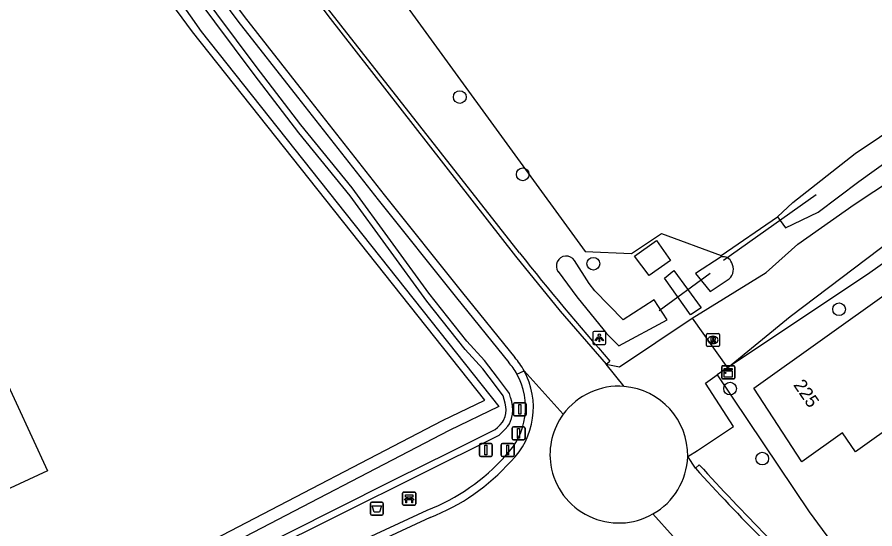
# Model space of a CAD drawing. Extents: x 164494 to 166241, y 382475 to 384494.
# Drawn here: x 165093.4 to 165159.3, y 383042.8 to 383082.1 of the extents above; entities that cross this region are included whole.
import ezdxf

# ---------------------------------------------------------------- set-up
doc = ezdxf.new("R2010")
doc.units = 0
for name, color, linetype in [('IMGEO_Afsluitpaal', 7, 'Continuous'), ('IMGEO_Afvalbak', 7, 'Continuous'), ('IMGEO_Bank', 7, 'Continuous'), ('IMGEO_Berm_halfverhard', 7, 'Continuous'), ('IMGEO_Boom', 7, 'Continuous'), ('IMGEO_Duiker', 7, 'Continuous'), ('IMGEO_Erf', 7, 'Continuous'), ('IMGEO_Grasland_overig', 7, 'Continuous'), ('IMGEO_Groenvoorziening', 7, 'Continuous'), ('IMGEO_Kast', 7, 'Continuous'), ('IMGEO_Lichtpunt', 7, 'Continuous'), ('IMGEO_Pand', 7, 'Continuous'), ('IMGEO_Pand_nummerreeks', 7, 'Continuous'), ('IMGEO_Rijbaan_lokaal_gesloten', 7, 'Continuous'), ('IMGEO_Rijbaan_lokaal_halfverhard', 7, 'Continuous'), ('IMGEO_Rijbaan_lokaal_open', 7, 'Continuous'), ('IMGEO_Rioolput', 7, 'Continuous'), ('IMGEO_Verkeersbordpaal', 7, 'Continuous'), ('IMGEO_Voetpad_open', 7, 'Continuous'), ('IMGEO_Waterloop', 7, 'Continuous')]:
    doc.layers.add(name, color=color, linetype=linetype)

msp = doc.modelspace()

# ---------------------------------------------------------------- linework, layer by layer
at = {"layer": 'IMGEO_Afsluitpaal'}
for p, q in [((165131.532, 383051.534), (165131.532, 383052.334)), ((165131.532, 383052.334), (165131.532, 383051.534)), ((165131.632, 383052.434), (165132.422, 383052.434)), ((165132.422, 383052.434), (165131.632, 383052.434)), ((165132.522, 383052.334), (165132.522, 383051.534)), ((165132.522, 383051.534), (165132.522, 383052.334)), ((165132.422, 383051.434), (165131.632, 383051.434)), ((165131.632, 383051.434), (165132.422, 383051.434)), ((165131.439, 383049.691), (165131.439, 383050.491)), ((165131.439, 383050.491), (165131.439, 383049.691)), ((165131.539, 383050.591), (165132.329, 383050.591)), ((165132.329, 383050.591), (165131.539, 383050.591)), ((165132.429, 383050.491), (165132.429, 383049.691)), ((165132.429, 383049.691), (165132.429, 383050.491)), ((165132.329, 383049.591), (165131.539, 383049.591)), ((165131.539, 383049.591), (165132.329, 383049.591)), ((165130.6, 383048.404), (165130.6, 383049.204)), ((165130.6, 383049.204), (165130.6, 383048.404)), ((165130.7, 383049.304), (165131.49, 383049.304)), ((165131.49, 383049.304), (165130.7, 383049.304)), ((165131.59, 383049.204), (165131.59, 383048.404)), ((165131.59, 383048.404), (165131.59, 383049.204)), ((165131.49, 383048.304), (165130.7, 383048.304)), ((165130.7, 383048.304), (165131.49, 383048.304))]:
    msp.add_line(p, q, dxfattribs=at)
for points in [[(165131.952, 383052.309), (165132.102, 383052.309), (165132.102, 383051.559), (165131.952, 383051.559), (165131.952, 383052.309)], [(165131.859, 383050.466), (165132.009, 383050.466), (165132.009, 383049.716), (165131.859, 383049.716), (165131.859, 383050.466)], [(165131.02, 383049.179), (165131.17, 383049.179), (165131.17, 383048.429), (165131.02, 383048.429), (165131.02, 383049.179)]]:
    msp.add_lwpolyline(points, dxfattribs=at)
for centre, start, end in [((165131.632, 383052.334), 90, 180), ((165131.632, 383052.334), 90, 180), ((165132.422, 383052.334), 0, 90), ((165132.422, 383052.334), 360, 90), ((165131.632, 383051.534), 180, 270), ((165131.632, 383051.534), 180, 270), ((165132.422, 383051.534), 270, 0), ((165132.422, 383051.534), 270, 0), ((165131.539, 383050.491), 90, 180), ((165131.539, 383050.491), 90, 180), ((165132.329, 383050.491), 0, 90), ((165132.329, 383050.491), 360, 90), ((165131.539, 383049.691), 180, 270), ((165131.539, 383049.691), 180, 270), ((165132.329, 383049.691), 270, 0), ((165132.329, 383049.691), 270, 0), ((165130.7, 383049.204), 90, 180), ((165130.7, 383049.204), 90, 180), ((165131.49, 383049.204), 0, 90), ((165131.49, 383049.204), 360, 90), ((165130.7, 383048.404), 180, 270), ((165130.7, 383048.404), 180, 270), ((165131.49, 383048.404), 270, 0), ((165131.49, 383048.404), 270, 0)]:
    msp.add_arc(centre, 0.1, start, end, dxfattribs=at)
at = {"layer": 'IMGEO_Afvalbak'}
for p, q in [((165120.552, 383043.897), (165120.552, 383044.697)), ((165120.552, 383044.697), (165120.552, 383043.897)), ((165120.652, 383044.797), (165121.442, 383044.797)), ((165121.442, 383044.797), (165120.652, 383044.797)), ((165121.542, 383044.697), (165121.542, 383043.897)), ((165121.542, 383043.897), (165121.542, 383044.697)), ((165121.442, 383043.797), (165120.652, 383043.797)), ((165120.652, 383043.797), (165121.442, 383043.797))]:
    msp.add_line(p, q, dxfattribs=at)
msp.add_lwpolyline([(165120.695, 383044.511), (165121.399, 383044.511), (165121.25, 383044.041), (165120.844, 383044.041), (165120.695, 383044.511)], dxfattribs=at)
for centre, start, end in [((165120.652, 383044.697), 90, 180), ((165120.652, 383044.697), 90, 180), ((165121.442, 383044.697), 0, 90), ((165121.442, 383044.697), 360, 90), ((165120.652, 383043.897), 180, 270), ((165120.652, 383043.897), 180, 270), ((165121.442, 383043.897), 270, 0), ((165121.442, 383043.897), 270, 0)]:
    msp.add_arc(centre, 0.1, start, end, dxfattribs=at)
at = {"layer": 'IMGEO_Bank'}
for p, q in [((165123.031, 383044.655), (165123.031, 383045.496)), ((165123.031, 383045.496), (165123.031, 383044.655)), ((165123.106, 383045.58), (165123.947, 383045.58)), ((165123.947, 383045.58), (165123.106, 383045.58)), ((165123.34, 383045.086), (165123.34, 383045.192)), ((165123.384, 383045.192), (165123.384, 383045.086)), ((165123.672, 383045.198), (165123.39, 383045.198)), ((165123.39, 383045.08), (165123.672, 383045.08)), ((165123.678, 383045.086), (165123.678, 383045.192)), ((165123.722, 383045.192), (165123.722, 383045.086)), ((165124.031, 383045.505), (165124.031, 383044.664)), ((165124.031, 383044.664), (165124.031, 383045.505)), ((165123.956, 383044.58), (165123.115, 383044.58)), ((165123.115, 383044.58), (165123.956, 383044.58)), ((165123.728, 383044.978), (165123.335, 383044.978))]:
    msp.add_line(p, q, dxfattribs=at)
for points in [[(165123.278, 383044.978), (165123.136, 383044.978), (165123.248, 383045.08), (165123.334, 383045.08)], [(165123.334, 383045.198), (165123.248, 383045.198), (165123.248, 383045.359), (165123.811, 383045.359), (165123.811, 383045.198), (165123.728, 383045.198)], [(165123.728, 383045.08), (165123.811, 383045.08), (165123.923, 383044.978), (165123.784, 383044.978)], [(165123.328, 383044.971), (165123.328, 383044.764), (165123.285, 383044.764), (165123.285, 383044.971)], [(165123.778, 383044.971), (165123.778, 383044.764), (165123.734, 383044.764), (165123.734, 383044.971)]]:
    msp.add_lwpolyline(points, dxfattribs=at)
for centre, radius, start, end in [((165123.109, 383045.502), 0.0779, 92.4484, 184.28452), ((165123.109, 383045.502), 0.0779, 92.4484, 184.28452), ((165123.333, 383045.191), 0.00671, 2.89567, 87.10433), ((165123.333, 383045.087), 0.00671, 272.89567, 357.10433), ((165123.39, 383045.191), 0.00671, 92.89567, 177.10433), ((165123.39, 383045.087), 0.00671, 182.89567, 267.10433), ((165123.672, 383045.191), 0.00671, 2.89567, 87.10433), ((165123.672, 383045.087), 0.00671, 272.89567, 357.10433), ((165123.729, 383045.191), 0.00671, 92.89567, 177.10433), ((165123.729, 383045.087), 0.00671, 182.89567, 267.10433), ((165123.953, 383045.502), 0.0779, 2.4484, 94.28452), ((165123.953, 383045.502), 0.0779, 2.4484, 94.28452), ((165123.109, 383044.658), 0.0779, 182.4484, 274.28452), ((165123.109, 383044.658), 0.0779, 182.4484, 274.28452), ((165123.278, 383044.971), 0.00671, 2.89567, 87.10433), ((165123.335, 383044.971), 0.00671, 92.89567, 177.10433), ((165123.727, 383044.971), 0.00671, 2.89567, 87.10433), ((165123.784, 383044.971), 0.00671, 92.89567, 177.10433), ((165123.953, 383044.658), 0.0779, 272.4484, 4.28452), ((165123.953, 383044.658), 0.0779, 272.4484, 4.28452)]:
    msp.add_arc(centre, radius, start, end, dxfattribs=at)
at = {"layer": 'IMGEO_Berm_halfverhard'}
for points in [[(165132.015, 383063.951), (165116.709, 383083.512), (165105.08, 383099.084), (165105.321, 383099.248), (165089.441, 383120.561), (165088.96, 383120.2)], [(165084.718, 383117.313), (165084.231, 383116.963), (165110.383, 383081.771), (165114.948, 383075.929), (165121.14, 383068.038), (165127.167, 383060.515), (165131.174, 383055.545)], [(165138.648, 383055.401), (165138.953, 383055.645)], [(165131.808, 383054.649), (165132.357, 383054.895)], [(165145.803, 383047.676), (165145.508, 383047.406)], [(165096.433, 383030.107), (165096.175, 383030.648), (165100.825, 383032.871), (165106.055, 383035.28), (165114.926, 383039.545), (165124.917, 383044.186)]]:
    msp.add_lwpolyline(points, dxfattribs=at)
for centre, radius, start, end in [((165276.772, 383177.816), 184.174, 218.18835, 221.55565), ((165127.203, 383052.063), 5.281, 29.31766, 41.24797), ((165127.24, 383052.092), 5.235, 314.72713, 29.2402), ((165119.296, 383058.656), 15.524, 291.23073, 318.51098), ((165289.884, 383179.211), 195.092, 222.39385, 226.82773)]:
    msp.add_arc(centre, radius, start, end, dxfattribs=at)
at = {"layer": 'IMGEO_Boom'}
for centre in [(165127.421, 383075.929), (165132.253, 383069.99), (165137.675, 383063.12), (165156.546, 383059.627), (165148.178, 383053.531), (165150.645, 383048.15)]:
    msp.add_circle(centre, 0.489, dxfattribs=at)
at = {"layer": 'IMGEO_Duiker'}
for points in [[(165147.666, 383063.397), (165154.789, 383068.446)], [(165142.728, 383059.518), (165146.652, 383062.389)]]:
    msp.add_lwpolyline(points, dxfattribs=at)
at = {"layer": 'IMGEO_Erf'}
msp.add_lwpolyline([(165092.654, 383033.657), (165109.176, 383042.267), (165126.099, 383051.085), (165129.346, 383052.646), (165106.891, 383080.948), (165095.917, 383095.847), (165095.148, 383097.711), (165091.308, 383102.836)], dxfattribs=at)
at = {"layer": 'IMGEO_Grasland_overig'}
for points in [[(165090.977, 383126.271), (165109.315, 383102.17), (165116.194, 383099.107), (165122.512, 383097.152), (165123.715, 383095.196), (165123.722, 383093.887), (165120.236, 383087.207), (165137.054, 383064.063), (165140.602, 383063.912), (165142.91, 383065.451), (165147.5, 383063.744), (165151.816, 383066.736)], [(165142.516, 383064.9), (165143.599, 383063.38), (165141.959, 383062.22), (165140.843, 383063.713), (165142.516, 383064.9)], [(165147.193, 383054.584), (165154.258, 383044.057), (165156.236, 383041.337), (165158.94, 383038.391), (165159.475, 383037.853), (165160.125, 383037.497), (165161.028, 383037.439), (165161.581, 383037.565), (165162.778, 383037.822), (165169.277, 383031.589)]]:
    msp.add_lwpolyline(points, dxfattribs=at)
at = {"layer": 'IMGEO_Groenvoorziening'}
for points in [[(165093.164, 383032.421), (165093.464, 383031.692), (165093.844, 383031.73), (165130.436, 383049.949), (165130.68, 383050.172), (165130.911, 383050.403), (165131.114, 383050.653), (165131.229, 383050.832), (165131.395, 383051.232), (165131.465, 383051.554), (165131.489, 383051.885), (165131.473, 383052.199), (165131.413, 383052.534), (165131.326, 383052.795), (165131.313, 383052.843), (165131.228, 383053.155), (165130.304, 383054.382), (165129.323, 383055.685), (165127.972, 383057.173), (165125.053, 383060.869), (165119.16, 383068.961), (165115.208, 383073.802), (165111.774, 383078.281), (165099.629, 383094.586)], [(165168.789, 383071.017), (165169.627, 383070.041), (165158.919, 383062.435), (165147.971, 383055.131)]]:
    msp.add_lwpolyline(points, dxfattribs=at)
at = {"layer": 'IMGEO_Kast'}
for p, q in [((165147.533, 383054.349), (165147.533, 383055.19)), ((165147.533, 383055.19), (165147.533, 383054.349)), ((165147.608, 383055.274), (165148.449, 383055.274)), ((165148.449, 383055.274), (165147.608, 383055.274)), ((165148.533, 383055.199), (165148.533, 383054.358)), ((165148.533, 383054.358), (165148.533, 383055.199)), ((165148.458, 383054.274), (165147.617, 383054.274)), ((165147.617, 383054.274), (165148.458, 383054.274))]:
    msp.add_line(p, q, dxfattribs=at)
for points in [[(165147.728, 383055.064), (165148.328, 383055.064), (165148.328, 383054.979), (165147.728, 383054.979), (165147.728, 383055.064)], [(165147.728, 383054.889), (165148.328, 383054.889), (165148.328, 383054.4), (165147.728, 383054.4), (165147.728, 383054.889)]]:
    msp.add_lwpolyline(points, dxfattribs=at)
msp.add_circle((165147.812, 383054.738), 0.0377, dxfattribs=at)
for centre, start, end in [((165147.611, 383055.196), 92.4484, 184.28452), ((165147.611, 383055.196), 92.4484, 184.28452), ((165148.455, 383055.196), 2.4484, 94.28452), ((165148.455, 383055.196), 2.4484, 94.28452), ((165147.611, 383054.352), 182.4484, 274.28452), ((165147.611, 383054.352), 182.4484, 274.28452), ((165148.455, 383054.352), 272.4484, 4.28452), ((165148.455, 383054.352), 272.4484, 4.28452)]:
    msp.add_arc(centre, 0.0779, start, end, dxfattribs=at)
at = {"layer": 'IMGEO_Lichtpunt'}
for p, q in [((165137.636, 383057.831), (165137.636, 383057.024)), ((165137.636, 383057.831), (165137.636, 383057.024)), ((165138.538, 383057.926), (165137.73, 383057.926)), ((165138.538, 383057.926), (165137.73, 383057.926)), ((165138.632, 383057.024), (165138.632, 383057.831)), ((165138.632, 383057.024), (165138.632, 383057.831)), ((165137.73, 383056.93), (165138.538, 383056.93)), ((165137.73, 383056.93), (165138.538, 383056.93))]:
    msp.add_line(p, q, dxfattribs=at)
for points in [[(165138.01, 383057.495), (165138.049, 383057.467), (165137.861, 383057.205), (165137.823, 383057.232), (165138.01, 383057.495)], [(165138.112, 383057.447), (165138.159, 383057.447), (165138.159, 383057.125), (165138.112, 383057.125), (165138.112, 383057.447)], [(165138.222, 383057.467), (165138.26, 383057.494), (165138.447, 383057.232), (165138.408, 383057.204), (165138.222, 383057.467)]]:
    msp.add_lwpolyline(points, dxfattribs=at)
msp.add_circle((165138.135, 383057.629), 0.0994, dxfattribs=at)
for centre, start, end in [((165137.73, 383057.831), 90, 180), ((165137.73, 383057.831), 90, 180), ((165138.538, 383057.831), 0, 90), ((165138.538, 383057.831), 0, 90), ((165137.73, 383057.024), 180, 270), ((165137.73, 383057.024), 180, 270), ((165138.538, 383057.024), 270, 0), ((165138.538, 383057.024), 270, 360)]:
    msp.add_arc(centre, 0.0946, start, end, dxfattribs=at)
at = {"layer": 'IMGEO_Pand'}
for points in [[(165175.747, 383061.481), (165157.81, 383048.67), (165156.806, 383050.136), (165153.692, 383047.912), (165150.009, 383053.561), (165170.909, 383068.487), (165175.747, 383061.481)], [(165086.419, 383042.886), (165082.794, 383050.728), (165092.141, 383055.049), (165095.767, 383047.208), (165086.419, 383042.886)]]:
    msp.add_lwpolyline(points, dxfattribs=at)
at = {"layer": 'IMGEO_Rijbaan_lokaal_gesloten'}
for points in [[(165088.96, 383120.2), (165104.824, 383098.91), (165117.287, 383082.185), (165131.701, 383063.704), (165135.116, 383059.491), (165138.648, 383055.401)], [(165084.718, 383117.313), (165110.865, 383082.129), (165115.42, 383076.3), (165121.609, 383068.413), (165127.634, 383060.891), (165131.641, 383055.922)], [(165132.357, 383054.895), (165135.361, 383051.557)], [(165140.043, 383053.693), (165138.648, 383055.401)], [(165145.508, 383047.406), (165144.918, 383048.309)], [(165142.252, 383043.9), (165146.939, 383038.692)], [(165125.134, 383043.627), (165115.179, 383039.001), (165106.315, 383034.739), (165101.084, 383032.33), (165096.433, 383030.107)]]:
    msp.add_lwpolyline(points, dxfattribs=at)
for centre, radius, start, end in [((165127.186, 383052.053), 5.9, 28.79297, 40.97362), ((165127.237, 383052.091), 5.837, 314.64205, 28.70823), ((165119.313, 383058.626), 16.089, 291.21019, 318.37004), ((165289.75, 383179.072), 195.299, 222.39036, 226.8272)]:
    msp.add_arc(centre, radius, start, end, dxfattribs=at)
at = {"layer": 'IMGEO_Rijbaan_lokaal_halfverhard'}
for points in [[(165145.275, 383058.943), (165150.953, 383062.462), (165153.384, 383064.628), (165157.699, 383067.663), (165165.264, 383072.659), (165174.96, 383079.683), (165177.631, 383081.868)], [(165147.971, 383055.131), (165152.793, 383059.072), (165161.607, 383065.761), (165168.789, 383071.017)], [(165145.275, 383058.943), (165147.971, 383055.131)]]:
    msp.add_lwpolyline(points, dxfattribs=at)
at = {"layer": 'IMGEO_Rijbaan_lokaal_open'}
for centre, radius, start, end in [((165139.608, 383048.447), 5.264, 85.26313, 143.78326), ((165139.613, 383048.405), 5.306, 358.9678, 85.3514), ((165139.606, 383048.449), 5.261, 143.78992, 188.67041), ((165139.631, 383048.495), 5.29, 299.69916, 357.98046), ((165139.63, 383048.496), 5.292, 189.13476, 299.70862)]:
    msp.add_arc(centre, radius, start, end, dxfattribs=at)
at = {"layer": 'IMGEO_Rioolput'}
for p, q in [((165146.354, 383056.843), (165146.354, 383057.695)), ((165146.429, 383057.769), (165147.281, 383057.769)), ((165146.842, 383057.549), (165146.867, 383057.549)), ((165147.355, 383057.695), (165147.355, 383056.843)), ((165146.865, 383056.989), (165146.84, 383056.989)), ((165147.281, 383056.769), (165146.429, 383056.769))]:
    msp.add_line(p, q, dxfattribs=at)
for points in [[(165146.354, 383056.843), (165146.354, 383057.695)], [(165146.429, 383057.769), (165147.281, 383057.769)], [(165147.355, 383057.695), (165147.355, 383056.843)], [(165146.943, 383057.467), (165146.691, 383057.469), (165146.691, 383057.069)], [(165146.691, 383057.069), (165146.815, 383057.069), (165146.815, 383057.231), (165146.826, 383057.231)], [(165146.869, 383057.388), (165146.815, 383057.388), (165146.815, 383057.307)], [(165146.815, 383057.307), (165146.867, 383057.307)], [(165146.873, 383057.202), (165146.944, 383057.069), (165147.084, 383057.069), (165147.019, 383057.195)], [(165147.281, 383056.769), (165146.429, 383056.769)]]:
    msp.add_lwpolyline(points, dxfattribs=at)
for centre, radius, start, end in [((165146.431, 383057.693), 0.0765, 91.55205, 178.44795), ((165146.431, 383057.693), 0.0765, 91.55205, 178.44795), ((165147.279, 383057.693), 0.0765, 1.55205, 88.44795), ((165147.279, 383057.693), 0.0765, 1.55205, 88.44795), ((165146.431, 383056.845), 0.0765, 181.55205, 268.44795), ((165146.431, 383056.845), 0.0765, 181.55205, 268.44795), ((165146.825, 383057.178), 0.0533, 26.02933, 88.69889), ((165146.851, 383057.496), 0.19, 274.7715, 282.96867), ((165146.875, 383057.292), 0.0964, 77.00612, 93.18647), ((165146.889, 383057.349), 0.0378, 276.66336, 79.67722), ((165146.942, 383057.357), 0.109, 350.36119, 89.41601), ((165146.94, 383057.357), 0.112, 277.58423, 350.98172), ((165146.924, 383057.142), 0.108, 29.51342, 73.79051), ((165147.279, 383056.845), 0.0765, 271.55205, 358.44795), ((165147.279, 383056.845), 0.0765, 271.55205, 358.44795)]:
    msp.add_arc(centre, radius, start, end, dxfattribs=at)
for centre, major_axis, ratio, start_param, end_param in [((165146.841, 383057.269), (-0.387, 0.002), 0.722429, 4.712389, 7.853982), ((165146.866, 383057.269), (-0.39, 0.002), 0.717154, 1.570796, 4.712389)]:
    msp.add_ellipse(centre, major_axis=major_axis, ratio=ratio, start_param=start_param, end_param=end_param, dxfattribs=at)
at = {"layer": 'IMGEO_Verkeersbordpaal'}
for p, q in [((165128.926, 383048.416), (165128.926, 383049.216)), ((165128.926, 383049.216), (165128.926, 383048.416)), ((165129.026, 383049.316), (165129.816, 383049.316)), ((165129.816, 383049.316), (165129.026, 383049.316)), ((165129.916, 383049.216), (165129.916, 383048.416)), ((165129.916, 383048.416), (165129.916, 383049.216)), ((165129.816, 383048.316), (165129.026, 383048.316)), ((165129.026, 383048.316), (165129.816, 383048.316))]:
    msp.add_line(p, q, dxfattribs=at)
msp.add_lwpolyline([(165129.346, 383049.191), (165129.496, 383049.191), (165129.496, 383048.441), (165129.346, 383048.441), (165129.346, 383049.191)], dxfattribs=at)
for centre, start, end in [((165129.026, 383049.216), 90, 180), ((165129.026, 383049.216), 90, 180), ((165129.816, 383049.216), 0, 90), ((165129.816, 383049.216), 360, 90), ((165129.026, 383048.416), 180, 270), ((165129.026, 383048.416), 180, 270), ((165129.816, 383048.416), 270, 0), ((165129.816, 383048.416), 270, 0)]:
    msp.add_arc(centre, 0.1, start, end, dxfattribs=at)
at = {"layer": 'IMGEO_Voetpad_open'}
for points in [[(165143.144, 383062.027), (165143.857, 383062.591), (165145.958, 383059.723), (165145.144, 383059.206), (165143.144, 383062.027)], [(165138.648, 383055.401), (165139.685, 383055.193), (165145.275, 383058.943)], [(165147.971, 383055.131), (165147.193, 383054.584)], [(165144.918, 383048.309), (165145.679, 383048.764), (165148.434, 383050.617), (165146.291, 383053.948), (165147.193, 383054.584)]]:
    msp.add_lwpolyline(points, dxfattribs=at)
at = {"layer": 'IMGEO_Waterloop'}
for points in [[(165095.862, 383097.667), (165107.563, 383080.96), (165130.416, 383052.157), (165126.591, 383050.318), (165109.675, 383041.504), (165093.574, 383033.113), (165093.951, 383032.199)], [(165108.902, 383039.744), (165117.664, 383044.153), (165122.515, 383046.586), (165126.698, 383048.665), (165130.143, 383050.378), (165130.324, 383050.544), (165130.529, 383050.748), (165130.705, 383050.94), (165130.771, 383051.071), (165130.902, 383051.386), (165130.955, 383051.628), (165130.974, 383051.891), (165130.961, 383052.14), (165130.911, 383052.421), (165130.834, 383052.7), (165130.746, 383052.975), (165130.149, 383053.767), (165129.183, 383055.051), (165127.836, 383056.535), (165124.899, 383060.253), (165119.009, 383068.341), (165115.061, 383073.177), (165111.62, 383077.665), (165099.476, 383093.969)], [(165151.816, 383066.736), (165153.002, 383067.83), (165157.78, 383071.582), (165165.334, 383076.665)], [(165151.816, 383066.736), (165152.431, 383065.873), (165154.937, 383067.079), (165158.049, 383069.441), (165166.126, 383075.223), (165165.334, 383076.665)], [(165147.5, 383063.641), (165145.517, 383062.375), (165146.633, 383060.983), (165148.111, 383061.958)], [(165142.339, 383060.346), (165139.956, 383058.825), (165137.798, 383061.043), (165137.358, 383061.6), (165136.219, 383063.365)], [(165134.978, 383062.514), (165136.395, 383060.57), (165138.515, 383057.986), (165138.691, 383057.772), (165139.625, 383056.807), (165143.338, 383058.809), (165142.339, 383060.346)]]:
    msp.add_lwpolyline(points, dxfattribs=at)
for centre, radius, start, end in [((165135.586, 383062.957), 0.753, 32.80757, 216.07221), ((165147.645, 383062.965), 0.692, 19.63125, 102.12535), ((165147.428, 383062.694), 1.004, 312.85537, 30.06953)]:
    msp.add_arc(centre, radius, start, end, dxfattribs=at)

# ---------------------------------------------------------------- texts
at = {"layer": 'IMGEO_Pand_nummerreeks'}
msp.add_text('225', height=1, rotation=304.42423, dxfattribs=at).set_placement((165152.999, 383053.809))

doc.saveas('drawing.dxf')
